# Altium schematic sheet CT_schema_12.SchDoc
size 387 x 385 mm
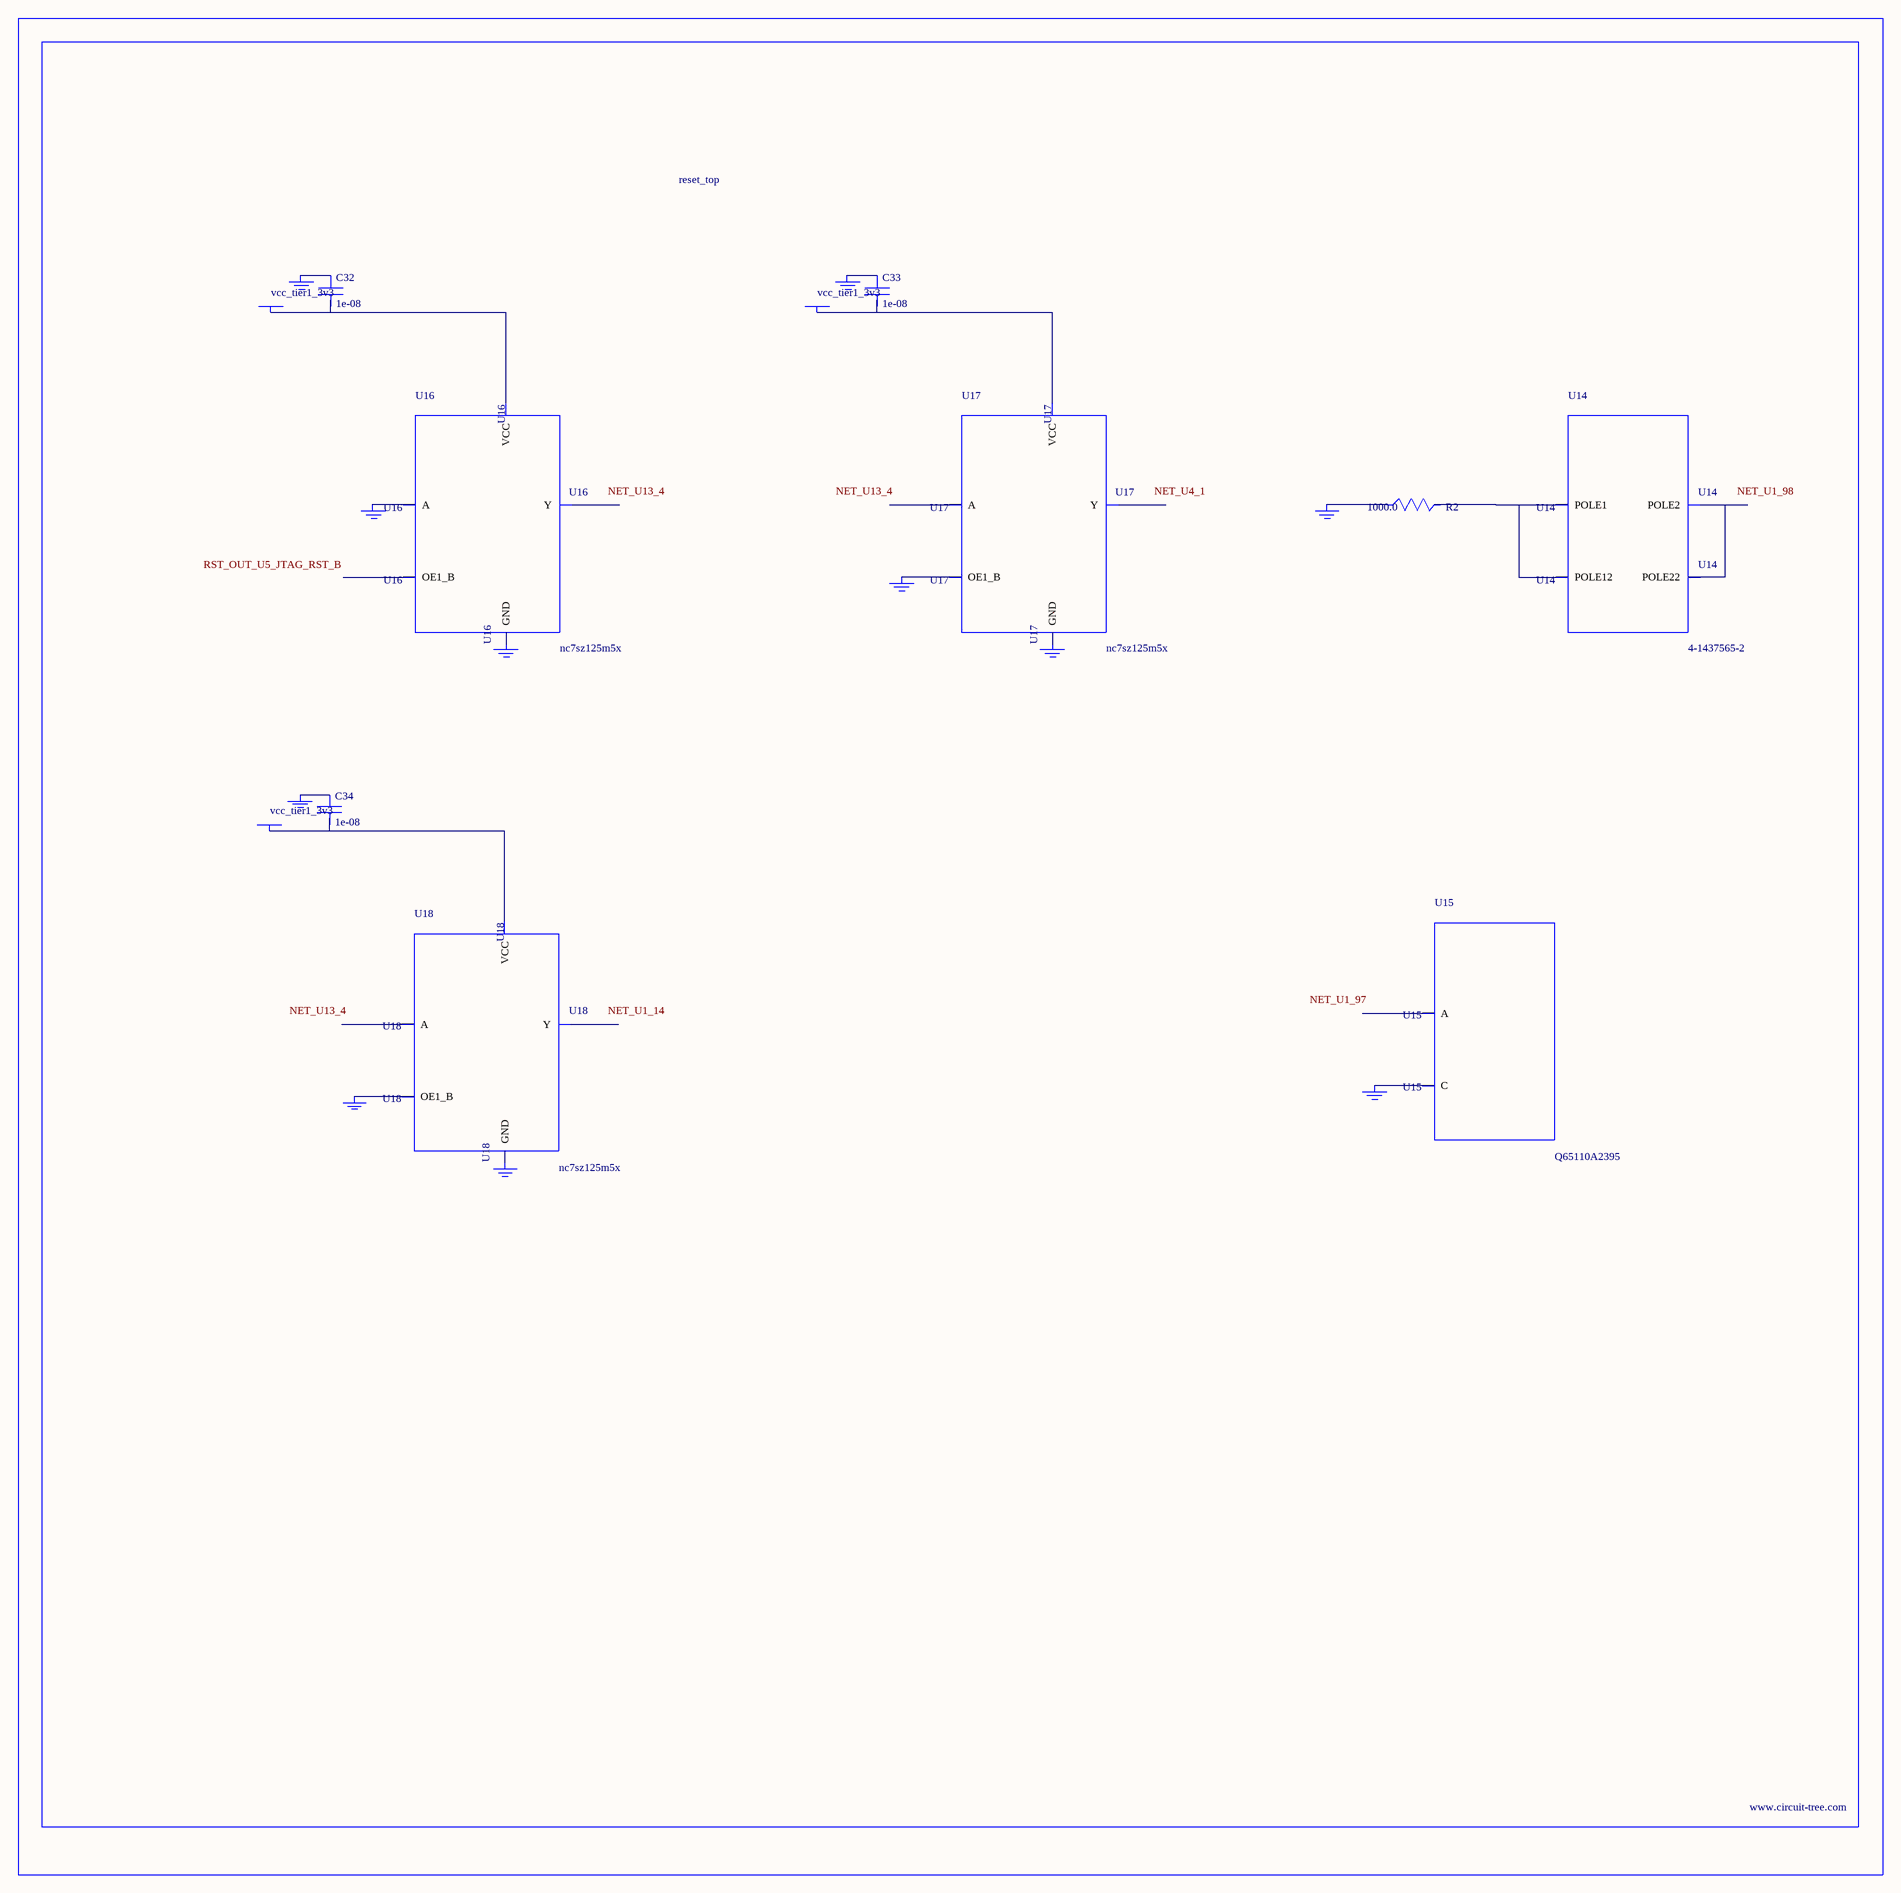
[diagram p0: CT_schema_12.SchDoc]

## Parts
BORDER11  (no value)
C32  1e-08  [C0402]
C33  1e-08  [C0402]
C34  1e-08  [C0402]
GND_INSTANCE_11_0  (no value)
GND_INSTANCE_11_1  (no value)
GND_INSTANCE_11_2  (no value)
GND_INSTANCE_11_3  (no value)
GND_INSTANCE_11_4  (no value)
GND_INSTANCE_11_5  (no value)
GND_INSTANCE_11_6  (no value)
GND_INSTANCE_11_7  (no value)
GND_INSTANCE_11_8  (no value)
GND_INSTANCE_11_9  (no value)
GND_INSTANCE_11_10  (no value)
POWER_INSTANCE_11_0  vcc_tier1_3v3
POWER_INSTANCE_11_1  vcc_tier1_3v3
POWER_INSTANCE_11_2  vcc_tier1_3v3
R2  1000.0  [R0603]
U14  4-1437565-2  [SW_4-1437565-2]
U15  Q65110A2395  [LGM67K-G1J2-24-Z]
U16  nc7sz125m5x  [NC7SZ125M5X]
U17  nc7sz125m5x  [NC7SZ125M5X]
U18  nc7sz125m5x  [NC7SZ125M5X]

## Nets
NetC32_1: C32.1 GND_INSTANCE_11_2.0(GND)
NetC32_2: C32.2 POWER_INSTANCE_11_0.0(PWR) U16.5(VCC)
NetC33_1: C33.1 GND_INSTANCE_11_5.0(GND)
NetC33_2: C33.2 POWER_INSTANCE_11_1.0(PWR) U17.5(VCC)
NetC34_1: C34.1 GND_INSTANCE_11_8.0(GND)
NetC34_2: C34.2 POWER_INSTANCE_11_2.0(PWR) U18.5(VCC)
NetGND_INSTANCE_11_0_0: GND_INSTANCE_11_0.0(GND) R2.1
NetGND_INSTANCE_11_1_0: GND_INSTANCE_11_1.0(GND) U15.C
NetGND_INSTANCE_11_3_0: GND_INSTANCE_11_3.0(GND) U16.2(A)
NetGND_INSTANCE_11_4_0: GND_INSTANCE_11_4.0(GND) U16.3(GND)
NetGND_INSTANCE_11_6_0: GND_INSTANCE_11_6.0(GND) U17.1(OE1_B)
NetGND_INSTANCE_11_7_0: GND_INSTANCE_11_7.0(GND) U17.3(GND)
NetGND_INSTANCE_11_9_0: GND_INSTANCE_11_9.0(GND) U18.1(OE1_B)
NetGND_INSTANCE_11_10_0: GND_INSTANCE_11_10.0(GND) U18.3(GND)
NetR2_2: R2.2 U14.1(POLE1) U14.2(POLE12)
NetU14_3: U14.3(POLE2) U14.4(POLE22)

Not connected (* = marked no-connect by the designer): U15 A; U16 1(OE1_B) 4(Y); U17 2(A) 4(Y); U18 2(A) 4(Y)

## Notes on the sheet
- Labels drawn without touching a wire or pin: NET_U1_14, NET_U1_97, NET_U1_98, NET_U4_1, NET_U13_4, RST_OUT_U5_JTAG_RST_B

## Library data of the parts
BORDER11 = BORDER_PAGE11
C32-C34 = C0402C103K3RAC
GND_INSTANCE_11_0-GND_INSTANCE_11_10 = GND
POWER_INSTANCE_11_0-POWER_INSTANCE_11_2 = PWR
R2 = RC0603JR-071KL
